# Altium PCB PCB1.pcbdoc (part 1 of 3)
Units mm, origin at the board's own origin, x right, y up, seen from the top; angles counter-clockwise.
Board outline 85.01 x 107.37 mm, 4 copper layers (Top Layer, Inner1, Inner2, Bottom Layer); 103 components, 145 nets, 660 pads, 277 vias.
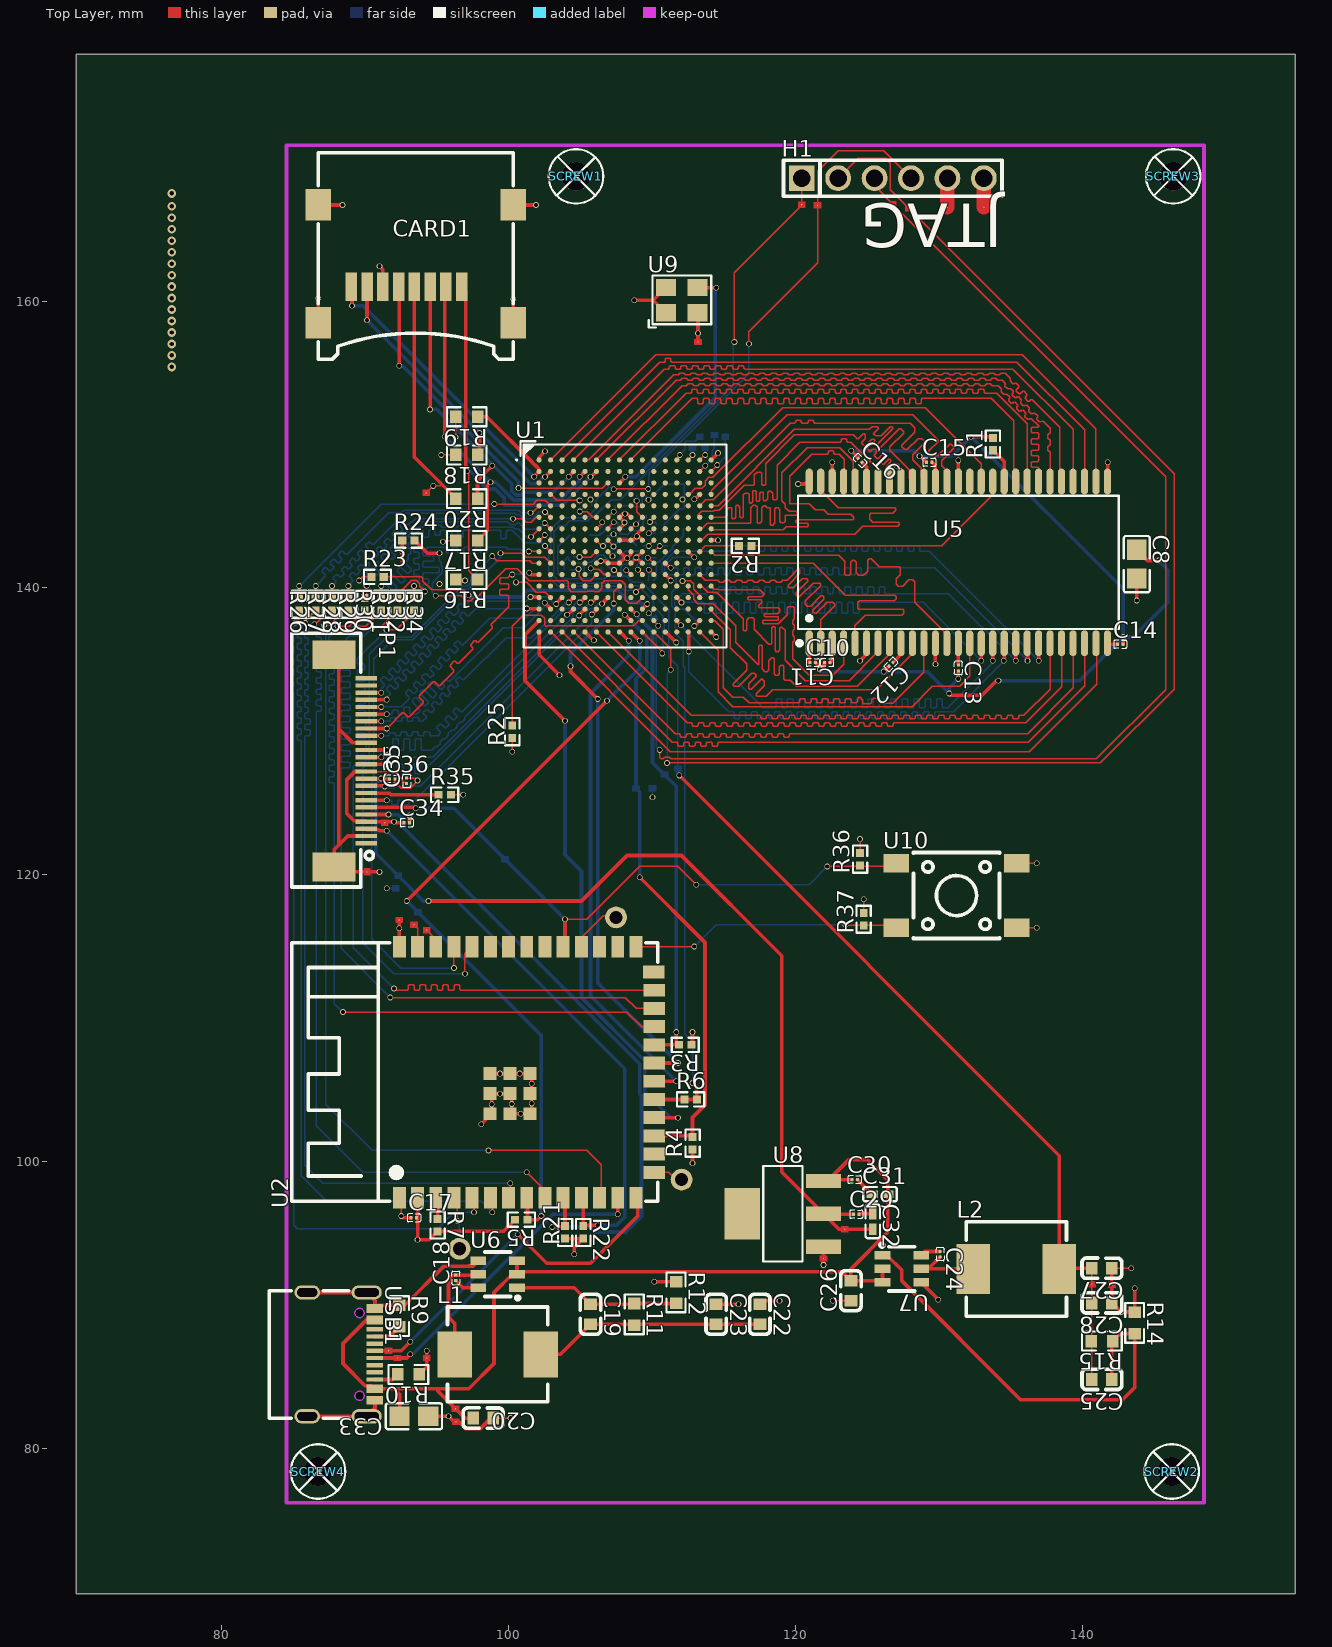
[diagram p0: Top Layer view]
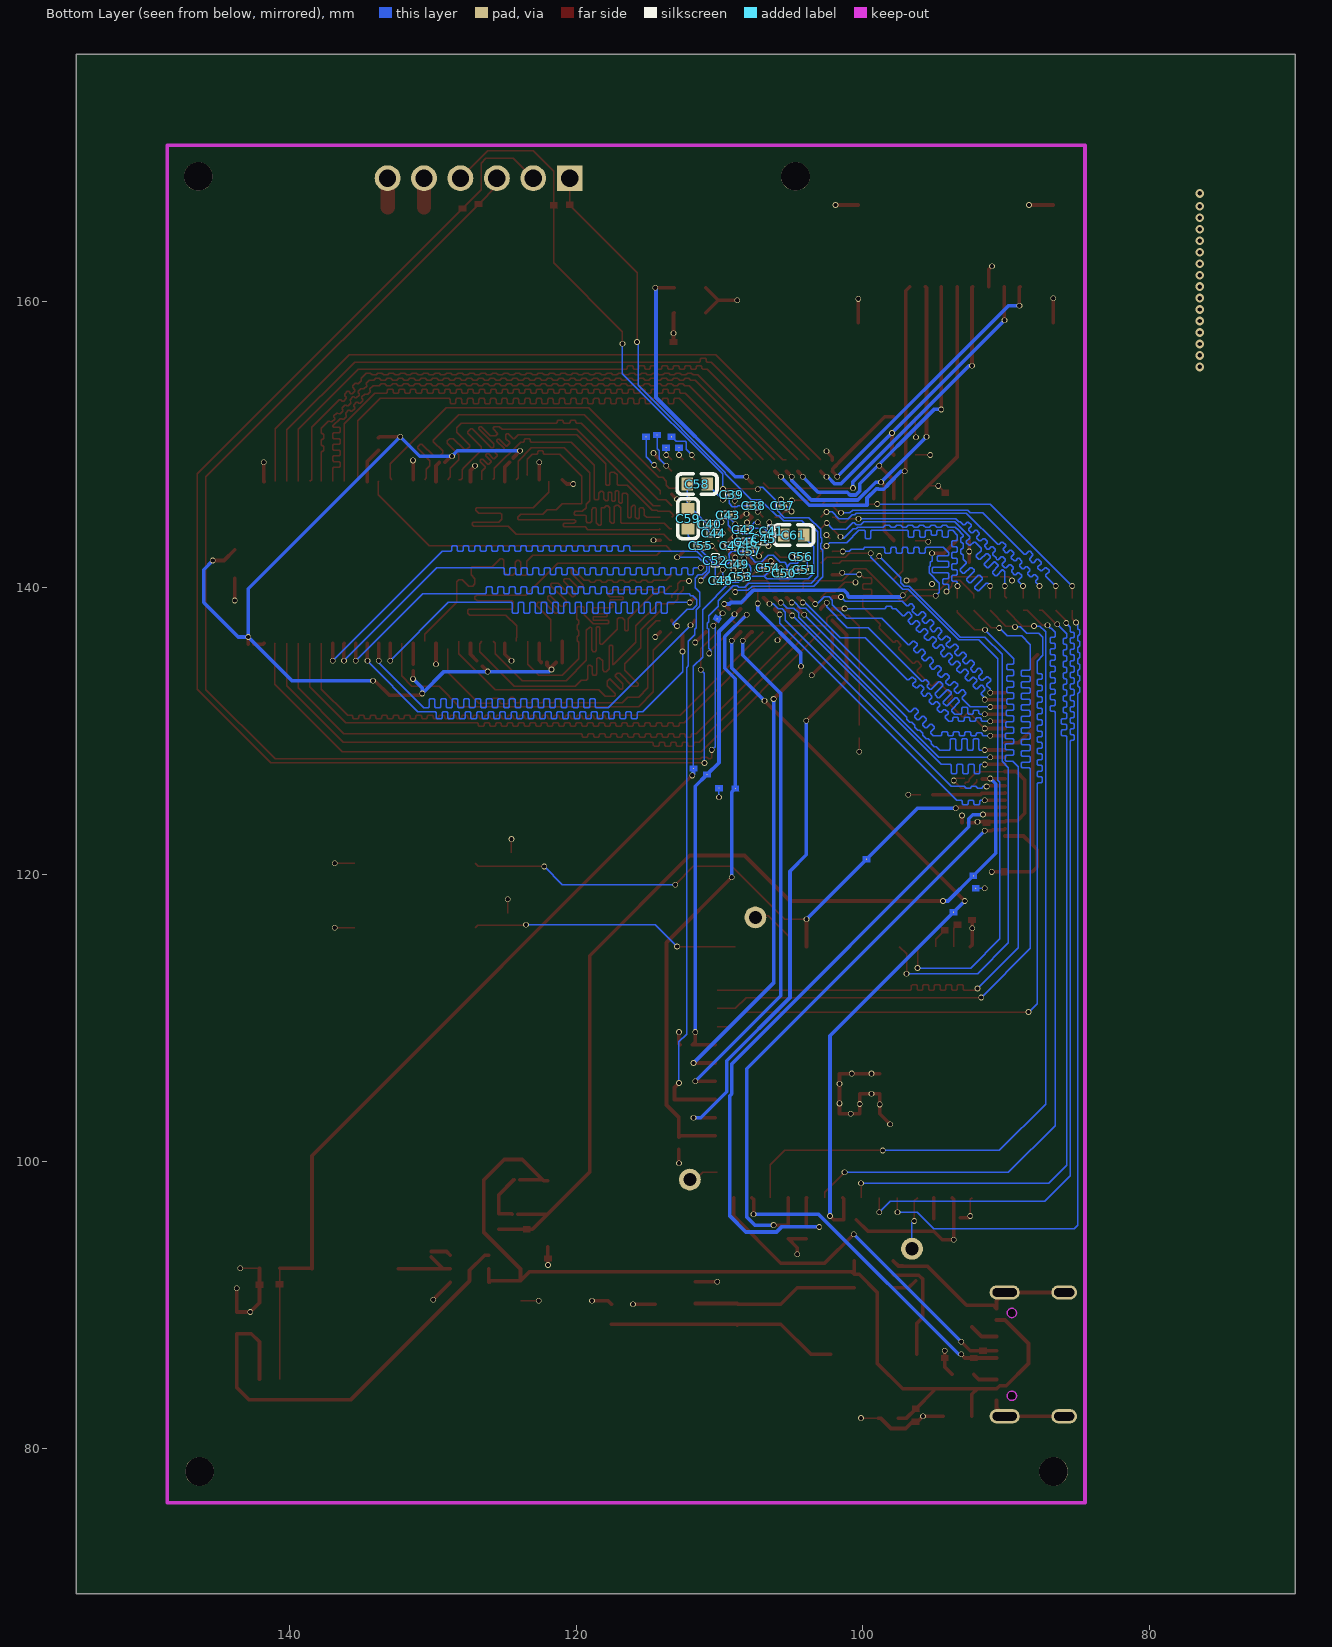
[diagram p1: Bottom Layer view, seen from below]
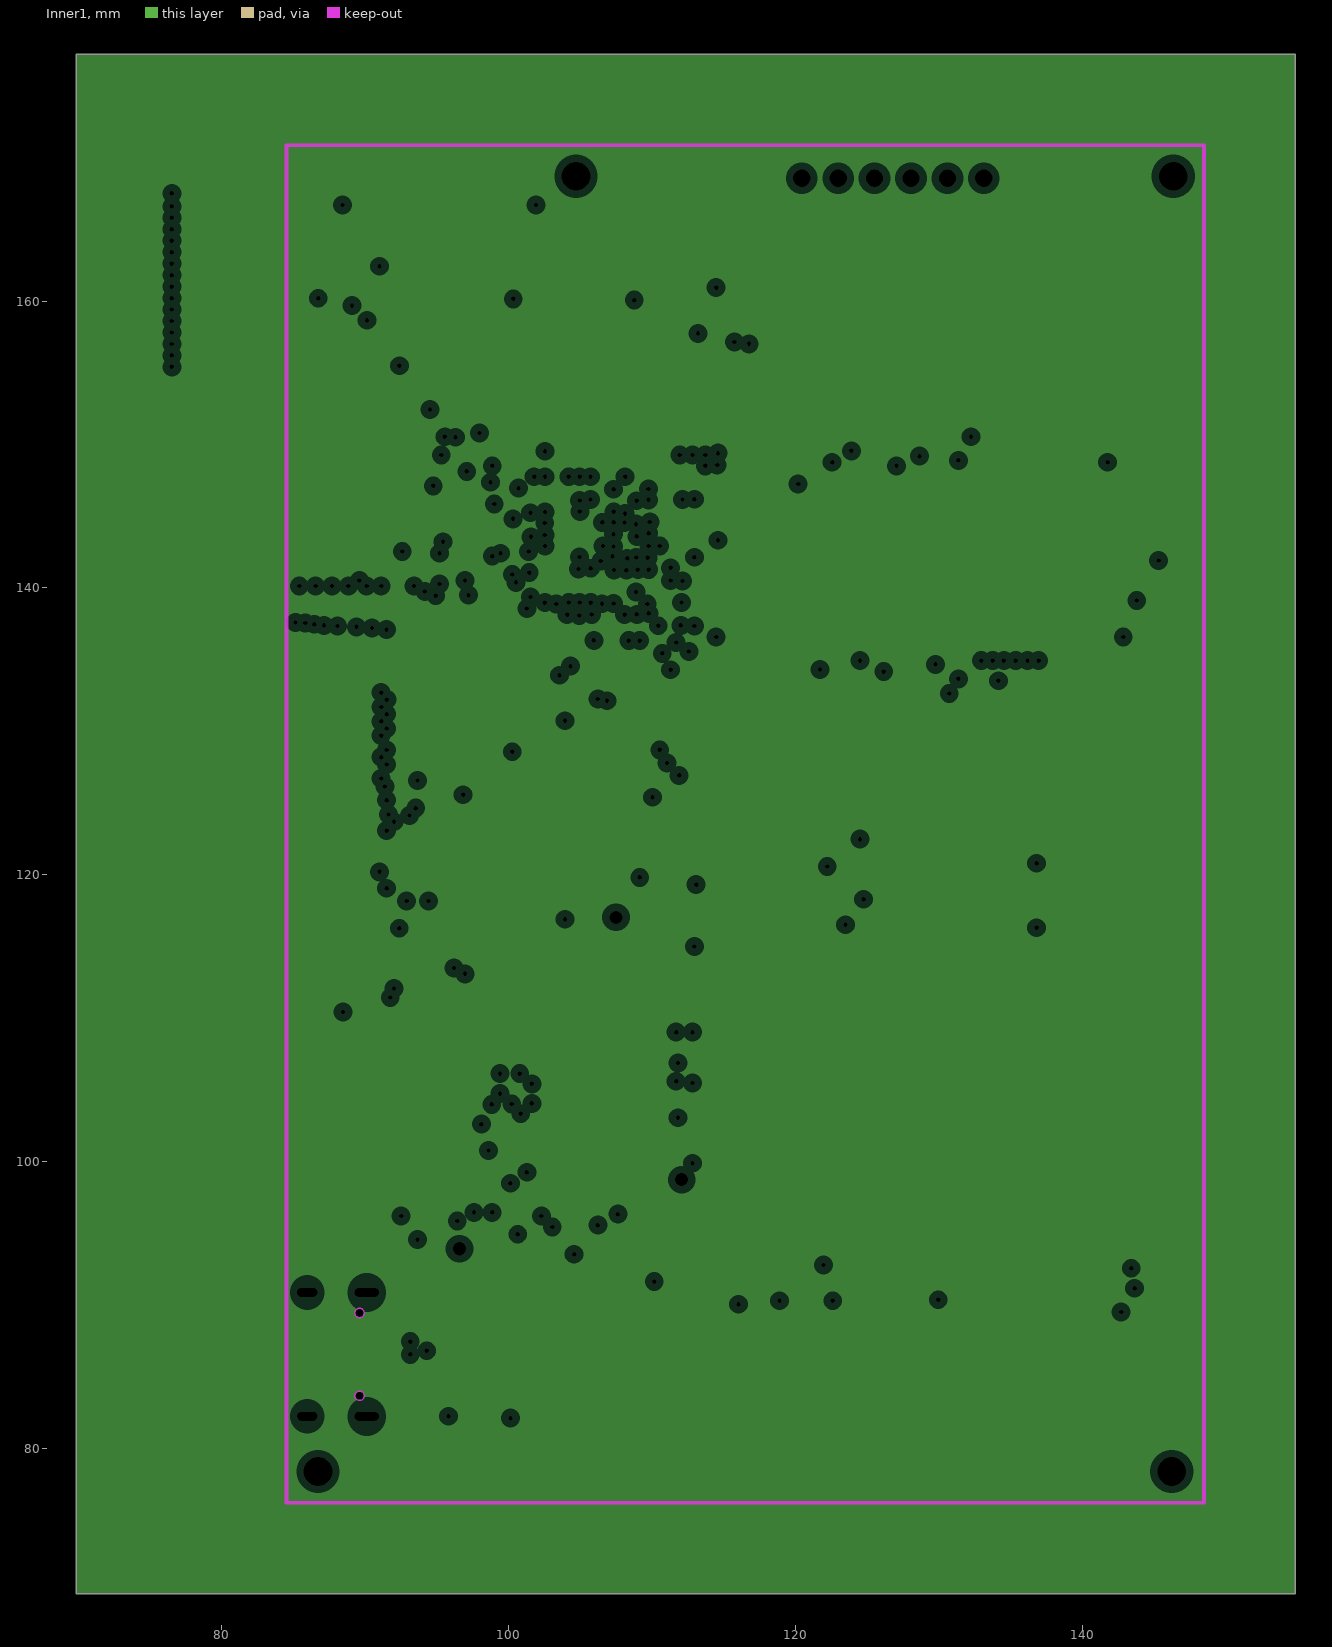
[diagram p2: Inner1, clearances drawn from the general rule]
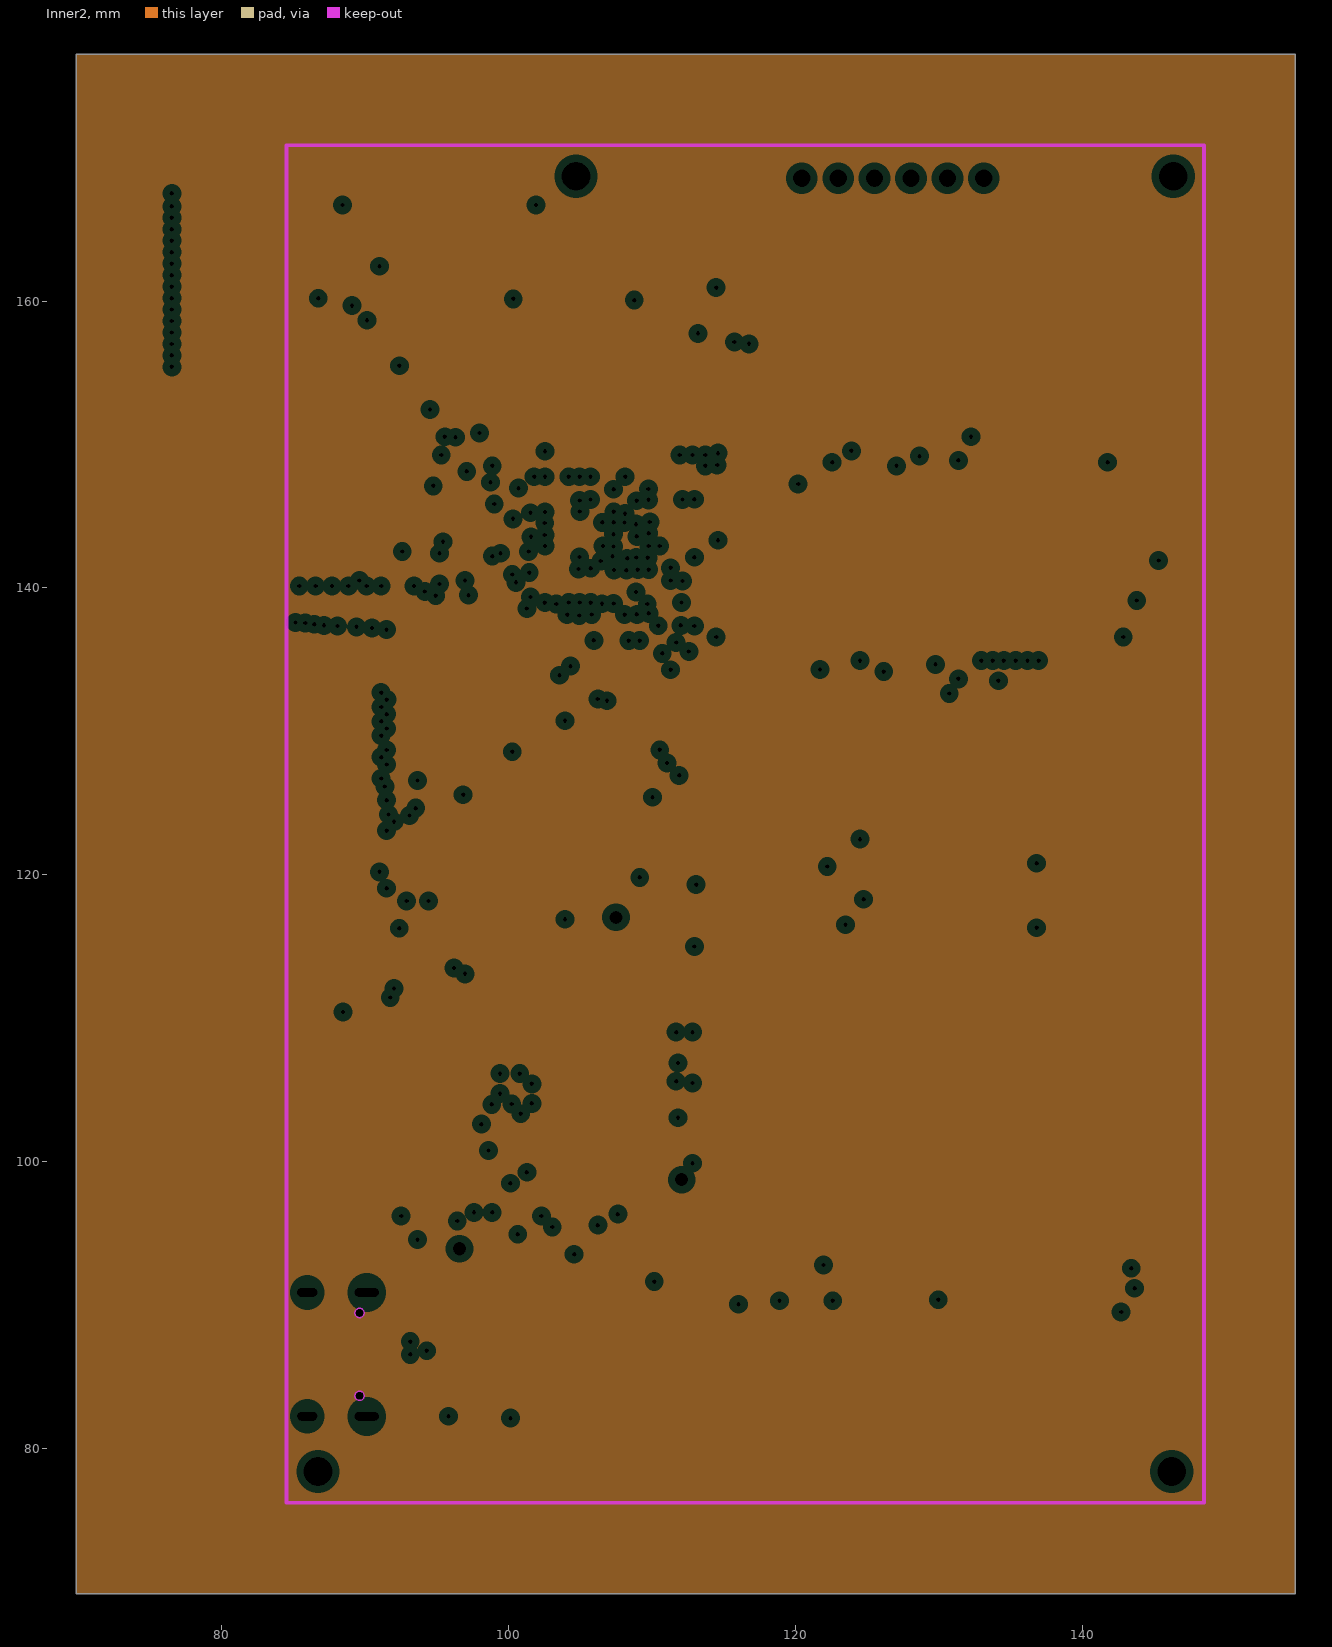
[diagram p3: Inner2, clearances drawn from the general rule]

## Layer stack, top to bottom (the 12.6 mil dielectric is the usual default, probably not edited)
Top Layer: signal copper (thickness not stored)
Dielectric: dielectric 0.32, FR-4, Dk 4.8
Inner1: plane copper (thickness not stored)
Dielectric: dielectric 0.32, FR-4, Dk 4.8
Inner2: plane copper (thickness not stored)
Dielectric: dielectric 0.32, FR-4, Dk 4.8
Bottom Layer: signal copper (thickness not stored)

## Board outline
154.856,69.85 69.85,69.85 69.85,177.216 154.856,177.216

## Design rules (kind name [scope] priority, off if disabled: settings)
BoardOutlineClearance copperThickness1oz [All] p0: genericclearance=0.254 ignorepadtopadclearanceinfootprint=FALSE except(0: Arc-SplitContinuation Track-SplitContinuation SMDPad-SplitContinuation THPad-SplitContinuation Via-SplitContinuation Fill-SplitContinuation Poly-SplitContinuation Region-SplitContinuation Text-SplitContinuation; 0.152: Track-CutoutEdge SMDPad-CutoutEdge THPad-CutoutEdge Via-CutoutEdge Region-CutoutEdge; 0.3: Track-OutlineEdge SMDPad-OutlineEdge THPad-OutlineEdge Via-OutlineEdge Fill-OutlineEdge Region-OutlineEdge Poly-OutlineEdge Text-OutlineEdge Fill-CutoutEdge)
BoardOutlineClearance copperThickness2oz [All] p0: genericclearance=0.254 ignorepadtopadclearanceinfootprint=FALSE except(0: Arc-SplitContinuation Track-SplitContinuation SMDPad-SplitContinuation THPad-SplitContinuation Via-SplitContinuation Fill-SplitContinuation Poly-SplitContinuation Region-SplitContinuation Text-SplitContinuation; 0.152: Track-CutoutEdge SMDPad-CutoutEdge THPad-CutoutEdge Via-CutoutEdge Region-CutoutEdge; 0.3: Track-OutlineEdge SMDPad-OutlineEdge THPad-OutlineEdge Via-OutlineEdge Fill-OutlineEdge Region-OutlineEdge Poly-OutlineEdge Text-OutlineEdge Fill-CutoutEdge)
Clearance copperThickness1oz [(InNet('SD_A0') OR InNet('SD_A1') OR InNet('SD_A2') OR InNet('SD_A3') OR InNet('SD_A4') OR InNet('SD_A5') OR InNet('SD_A6') OR InNet('SD_A7') OR InNet('SD_A8') OR InNet('SD_A9') OR InNet('SD_A10') OR InNet('SD_A11') OR InNet('SD_A12') OR InNet('SD_DQ15') OR InNet('SD_DQ14') OR InNet('SD_DQ8') OR InNet('SD_BA0') OR InNet('SD_BA1') OR InNet('SD_DQ9') OR InNet('SD_DQ7') OR InNet('SD_CLK') OR InNet('SD_WE_N') OR InNet('SD_DQ10') OR InNet('SD_CAS_N') OR InNet('SD_DQM1') OR InNet('SD_DQ2') OR InNet('SD_DQ3') OR InNet('SD_DQ11') OR InNet('SD_DQ12') OR InNet('SD_DQ13') OR InNet('SD_DQ0') OR InNet('SD_DQ1') OR InNet('SD_CS_N') OR InNet('SD_RAS_N') OR InNet('SD_DQ4') OR InNet('SD_DQ6') OR InNet('$1N9241') OR InNet('$1N9192') OR InNet('GND') OR InNet('$1N9142') OR InNet('SD_DQ5') OR InNet('$1N9091') OR InNet('SD_DQM0') OR InNet('$1N9039') OR InNet('$1N8986') OR InNet('$1N8318') OR InNet('$1N9437') OR InNet('$1N9341') OR InNet('+3V3') OR InNet('$1N11348') OR InNet('DOUT') OR InNet('DIN') OR InNet('CCLK') OR InNet('DONE') OR InNet('PROGRAMN') OR InNet('INITN') OR InNet('$1N11975') OR InNet('DN') OR InNet('DP') OR InNet('$1N14459') OR InNet('$1N14416') OR InNet('$1N14567') OR InNet('+5V') OR InNet('$1N16833') OR InNet('$1N16832') OR InNet('+1V1') OR InNet('$1N16834') OR InNet('+1V8') OR InNet('$1N17349') OR InNet('$1N12557') OR InNet('$1N12553') OR InNet('M_D2') OR InNet('M_D3') OR InNet('M_CMD') OR InNet('M_CLK') OR InNet('M_D0') OR InNet('M_D1') OR InNet('SDA') OR InNet('SCL') OR InNet('RESET') OR InNet('VSYNC') OR InNet('HREF') OR InNet('Y9') OR InNet('MCLK') OR InNet('Y8') OR InNet('Y7') OR InNet('PCLK') OR InNet('Y6') OR InNet('Y2') OR InNet('Y5') OR InNet('Y3') OR InNet('Y4') OR InNet('$1N14571') OR InNet('$1N24422') OR InNet('$1N24377') OR InNet('$1N24492') OR InNet('CRYSTAL') OR InNet('SSPI_CS_N') OR InNet('D0') OR InNet('D1') OR InNet('D2') OR InNet('D4') OR InNet('D3') OR InNet('D5') OR InNet('D6') OR InNet('D7') OR InNet('RX') OR InNet('TX') OR InNet('$1N29790') OR InNet('$1N29833') OR InNet('$1N29916') OR InNet('$1N29959') OR InNet('$1N30002') OR InNet('$1N30085') OR InNet('$1N30089') OR InNet('$1N30093') OR InNet('TDO') OR InNet('TDI') OR InNet('TMS') OR InNet('TCK') OR InNet('$1N33205') OR InNet('PROGRAM') OR InNet('$1N36431') OR InNet('$1N36646') OR InNet('$1N36895') OR InNet('$1N37600') OR InNet('$1N37295') OR InNet('$1N36495') OR InNet('$1N36690') OR InNet('$1N36953') OR InNet('$1N37637') OR InNet('$1N37245') OR InNet('$1N37470') OR InNet('$1N36752') OR InNet('$1N37409') OR InNet('$1N36552') OR InNet('$1N37361') OR InNet('$1N36571') OR InNet('$1N36807') OR InNet('$1N37097') OR InNet('$1N37518') OR InNet('$1N37345') OR InNet('$1N37150') OR InNet('$1N47813') OR InNet('$1N41066'))] p1: gap=0.178 ignorepadtopadclearanceinfootprint=FALSE except(0.099: Track-Track; 0.152: Track-SMDPad SMDPad-SMDPad Track-THPad SMDPad-THPad THPad-THPad Track-Via SMDPad-Via THPad-Via Via-Via SMDPad-Fill THPad-Fill Via-Fill Fill-Fill Track-Region SMDPad-Region THPad-Region Via-Region Region-Region Track-Poly SMDPad-Poly THPad-Poly Via-Poly Fill-Poly Region-Poly Poly-Poly Track-Text SMDPad-Text THPad-Text Via-Text Fill-Text Region-Text Poly-Text Text-Text; 0.175: Track-Hole SMDPad-Hole THPad-Hole Via-Hole Fill-Hole Region-Hole Poly-Hole Text-Hole Sheet-Hole; 0.3: Track-Fill Fill-Region Track-Sheet SMDPad-Sheet THPad-Sheet Via-Sheet Fill-Sheet Region-Sheet Poly-Sheet Text-Sheet)
Clearance copperThickness2oz [All] p1: gap=0.178 ignorepadtopadclearanceinfootprint=FALSE except(0.152: Track-SMDPad SMDPad-SMDPad Track-THPad SMDPad-THPad THPad-THPad Track-Via SMDPad-Via THPad-Via Via-Via SMDPad-Fill THPad-Fill Via-Fill Fill-Fill Track-Region SMDPad-Region THPad-Region Via-Region Region-Region Track-Poly SMDPad-Poly THPad-Poly Via-Poly Fill-Poly Region-Poly Poly-Poly Track-Text SMDPad-Text THPad-Text Via-Text Fill-Text Region-Text Poly-Text Text-Text; 0.175: Track-Hole SMDPad-Hole THPad-Hole Via-Hole Fill-Hole Region-Hole Poly-Hole Text-Hole Sheet-Hole; 0.203: Track-Track; 0.3: Track-Fill Fill-Region Track-Sheet SMDPad-Sheet THPad-Sheet Via-Sheet Fill-Sheet Region-Sheet Poly-Sheet Text-Sheet)
DiffPairsRouting differentialPair [All] p1: maxuncoupledlength=10 minlimit=6 maxlimit=6 mostfreqgap=6 toplayer_minwidth=5 toplayer_prefwidth=10 toplayer_maxwidth=100 bottomlayer_minwidth=5 bottomlayer_prefwidth=10 bottomlayer_maxwidth=100
PasteMaskExpansion pasteMaskExpansion [All] p1: expansion=0
PlaneConnect innerPlane [All] p1: planeconnectstyle=Relief reliefexpansion=0.508 reliefentries=4 reliefconductorwidth=0.254 reliefairgap=0.254
PolygonConnect copperRegion [All] p1: connectstyle=Relief reliefentries=4 reliefconductorwidth=10 polygonreliefangle="90 Angle" airgapwidth=10
RoutingVias viaSize [All] p1: viastyle="Through Hole" holewidth=11.811 minholewidth=11.811 maxholewidth=248.0314 width=15.748 minwidth=15.748 maxwidth=393.7008
SolderMaskExpansion solderMaskExpansion [All] p1: useseparateexpansions=TRUE expansion=2 expansionbottom=2
Width copperThickness1oz [All] p1: maxlimit=100 minlimit=4 preferedwidth=4
Width copperThickness2oz [All] p1: maxlimit=100 minlimit=8 preferedwidth=10

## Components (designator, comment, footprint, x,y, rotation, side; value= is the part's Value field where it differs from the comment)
C8 "CL21A476MQYNNNE" C0805 143.815,141.656 r270 top
C10 "GRM022R60J104KE15D" C01005 121.209,134.798 r0 top
C11 "GRM022R60J104KE15D" C01005 122.225,134.798 r180 top
C12 "GRM022R60J104KE15D" C01005 126.67,134.671 r225 top
C13 "GRM022R60J104KE15D" C01005 131.369,134.417 r270 top
C14 "GRM022R60J104KE15D" C01005 142.672,136.068 r0 top
C15 "GRM022R60J104KE15D" C01005 129.337,148.768 r0 top
C16 "GRM022R60J104KE15D" C01005 124.511,148.895 r315 top
C17 "GRM022R60J104KE15D" C01005 93.396,96.063 r0 top
C18 "GRM022R60J104KE15D" C01005 96.317,91.872 r90 top
C19 "TCC0603X7R104K500CT" C0603 105.715,89.332 r270 top
C20 "TCC0603X5R226M6R3CT" C0603 98.222,82.093 r180 top
C22 "TCC0603X5R226M6R3CT" C0603 117.526,89.332 r270 top
C23 "TCC0603X5R226M6R3CT" C0603 114.478,89.332 r270 top
C24 "GRM022R60J104KE15D" C01005 130.099,93.523 r270 top
C25 "TCC0603X7R104K500CT" C0603 141.381,84.799 r180 top
C26 "TCC0603X5R226M6R3CT" C0603 123.876,90.983 r90 top
C27 "TCC0603X5R226M6R3CT" C0603 141.381,92.546 r180 top
C28 "TCC0603X5R226M6R3CT" C0603 141.381,90.133 r180 top
C29 "GRM022R60J104KE15D" C01005 124.257,96.317 r0 top
C30 "GRM022R60J104KE15D" C01005 124.13,98.73 r0 top
C31 "GRM155R60J106ME44D" C0402 125.908,97.714 r0 top
C32 "GRM155R60J106ME44D" C0402 125.4,95.809 r270 top
C33 "CL21A476MQYNNNE" C0805 93.396,82.22 r180 top
C34 "GRM022R60J104KE15D" C01005 92.888,123.622 r0 top
C35 "GRM022R60J104KE15D" C01005 92.888,126.543 r90 top
C36 "GRM022R60J104KE15D" C01005 91.872,126.67 r0 top
C37 "GRM022R60J104KE15D" C01005 105.588,145.72 r180 bottom
C38 "GRM022R60J104KE15D" C01005 107.62,145.72 r180 bottom
C39 "GRM022R60J104KE15D" C01005 109.144,146.482 r180 bottom
C40 "GRM022R60J104KE15D" C01005 110.668,144.45 r180 bottom
C41 "GRM022R60J104KE15D" C01005 106.35,143.942 r90 bottom
C42 "GRM022R60J104KE15D" C01005 108.255,144.069 r180 bottom
C43 "GRM022R60J104KE15D" C01005 109.398,145.085 r180 bottom
C44 "GRM022R60J104KE15D" C01005 110.414,143.815 r180 bottom
C45 "GRM022R60J104KE15D" C01005 106.858,143.434 r270 bottom
C46 "GRM022R60J104KE15D" C01005 108.128,143.18 r180 bottom
C47 "GRM022R60J104KE15D" C01005 109.144,142.926 r0 bottom
C48 "GRM022R60J104KE15D" C01005 109.906,140.513 r0 bottom
C49 "GRM022R60J104KE15D" C01005 108.763,141.656 r180 bottom
C50 "GRM022R60J104KE15D" C01005 105.486,141.021 r180 bottom
C51 "GRM022R60J104KE15D" C01005 104.064,141.275 r180 bottom
C52 "GRM022R60J104KE15D" C01005 110.287,141.91 r270 bottom
C53 "GRM022R60J104KE15D" C01005 108.509,140.767 r180 bottom
C54 "GRM022R60J104KE15D" C01005 106.604,141.402 r180 bottom
C55 "GRM022R60J104KE15D" C01005 111.303,142.926 r0 bottom
C56 "GRM022R60J104KE15D" C01005 104.318,142.164 r180 bottom
C57 "GRM022R60J104KE15D" C01005 107.874,142.545 r0 bottom
C58 "TCC0603X5R226M6R3CT" C0603 111.557,147.244 r180 bottom
C59 "TCC0603X5R226M6R3CT" C0603 112.192,144.831 r90 bottom
C61 "TCC0603X5R226M6R3CT" C0603 104.826,143.688 r180 bottom
CARD1 "DS1139-06-08SS4BSR" TF-SMD_DS1139-06-08SS4BSR 93.523,162.611 r0 top
H1 "2.54-1x6P直针" HDR-TH_6P-P2.54-V-M-1 126.797,168.58 r0 top
L1 "FXL0630-6R8-M" IND-SMD_L7.0-W6.6 99.238,86.538 r0 top
L2 "FXL0630-100-M" IND-SMD_L7.3-W6.8 135.417,92.501 r0 top
P1 "AFC07-S24FCC-00" FPC-SMD_AFC07-S24FCC-00 88.951,127.94 r270 top
R1 "0402WGF1002TCE" R0402 133.782,150.038 r90 top
R2 "0402WGF330JTCE" R0402 116.51,142.926 r180 top
R3 "0402WGF1002TCE" R0402 112.319,108.128 r180 top
R4 "0402WGF1002TCE" R0402 112.827,101.27 r90 top
R5 "0402WGF1002TCE" R0402 100.889,95.936 r180 top
R6 "0402WGF330JTCE" R0402 112.7,104.318 r0 top
R7 "0402WGF1002TCE" R0402 95.047,95.555 r270 top
R9 "0603WAF5101T5E" R0603 92.38,89.205 r270 top
R10 "0603WAF5101T5E" R0603 93.015,85.141 r180 top
R11 "FRC0603F1963TS" R0603 108.763,89.332 r270 top
R12 "FRC0603F6202TS" R0603 111.684,90.856 r270 top
R14 "FRC0603F6202TS" R0603 143.667,88.736 r270 top
R15 "0603WAF2322T5E" R0603 141.381,87.466 r180 top
R16 "FRC0603F6202TS" R0603 97.075,140.589 r180 top
R17 "FRC0603F6202TS" R0603 97.079,143.307 r180 top
R18 "FRC0603F6202TS" R0603 97.079,149.276 r180 top
R19 "FRC0603F6202TS" R0603 97.079,151.943 r180 top
R20 "FRC0603F6202TS" R0603 97.079,146.228 r180 top
R21 "0402WGF1002TCE" R0402 103.937,95.047 r270 top
R22 "0402WGF1002TCE" R0402 105.207,95.047 r270 top
R23 "0402WGF1002TCE" R0402 90.856,140.767 r0 top
R24 "0402WGF1002TCE" R0402 93.015,143.307 r0 top
R25 "0402WGF1002TCE" R0402 100.254,129.972 r90 top
R26 "0402WGF330JTCE" R0402 85.395,138.862 r270 top
R27 "0402WGF330JTCE" R0402 86.538,138.862 r270 top
R28 "0402WGF330JTCE" R0402 87.681,138.862 r270 top
R29 "0402WGF330JTCE" R0402 88.824,138.862 r270 top
R30 "0402WGF330JTCE" R0402 89.967,138.862 r270 top
R31 "0402WGF330JTCE" R0402 91.11,138.862 r270 top
R32 "0402WGF330JTCE" R0402 92.253,138.862 r270 top
R34 "0402WGF330JTCE" R0402 93.396,138.862 r270 top
R35 "0402WGF1002TCE" R0402 95.541,125.576 r0 top
R36 "0402WGF1002TCE" R0402 124.511,121.082 r90 top
R37 "0402WGF1002TCE" R0402 124.765,116.891 r90 top
SCREW1 "Screw-Hole-M2" Screw-Hole-M2 104.699,168.707 r0 top
SCREW2 "Screw-Hole-M2" Screw-Hole-M2 146.255,78.368 r0 top
SCREW3 "Screw-Hole-M2" Screw-Hole-M2 146.355,168.707 r0 top
SCREW4 "Screw-Hole-M2" Screw-Hole-M2 86.707,78.368 r0 top
U1 "LFE5U-25F-6BG256C" CABGA-256_L14.0-W14.0-R16-C16-P0.80-TL 108.128,142.926 r0 top
U2 "ESP32-S3-WROOM-1-N16R2" WIRELM-SMD_ESP32-S3-WROOM-1 101.27,106.223 r90 top
U5 "W9825G6KH-6" TSOP-54_L22.2-W10.2-P0.80-LS11.8-BL 131.369,141.783 r0 top
U6 "AP63200WU-7" SOT-23-6_L2.9-W1.6-P0.95-LS2.8-BR 99.238,92.126 r0 top
U7 "AP63200WU-7" SOT-23-6_L2.9-W1.6-P0.95-LS2.8-BR 127.432,92.507 r180 top
U8 "AMS1117-1.8_C6185" SOT-223-4_L6.5-W3.5-P2.30-LS7.0-BR 119.13,96.346 r0 top
U9 "XOS32024000LT00351005" OSC-SMD_4P-L3.2-W2.5-BL 112.065,160.071 r0 top
U10 "TPS645-5NC60" SW-SMD_4P-L6.0-W6.0-P4.50-LS9.2 131.242,118.542 r0 top
USB1 "TYPE-C16PIN" USB-C-SMD_TYPE-C16PIN 88.316,86.538 r270 top

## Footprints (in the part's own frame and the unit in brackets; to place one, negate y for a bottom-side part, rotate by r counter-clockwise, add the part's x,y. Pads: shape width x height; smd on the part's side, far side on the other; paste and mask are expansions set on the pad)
C0402 [mm]
  rect 0.79x0.54 smd: 1(-0.545,0) 2(0.545,0)
  silkscreen extent -1.17,-0.5 1.17,0.5
C0603 [mm]
  rect 0.8x0.9 smd: 1(-0.7,0) 2(0.7,0)
  silkscreen extent -1.39,-0.71 1.39,0.71
C0805 [mm]
  rect 1.41x1.35 smd: 1(-1,0) 2(1,0)
  silkscreen extent -1.96,-0.9 1.96,0.9
C01005 [mm]
  rect 0.21x0.22 smd: 1(-0.195,0) 2(0.195,0)
  silkscreen extent -0.46,-0.27 0.46,0.27
CABGA-256_L14.0-W14.0-R16-C16-P0.80-TL [mm]
  round 0.36 smd: A1(-6,6) A2(-5.2,6) A3(-4.4,6) A4(-3.6,6) A5(-2.8,6) A6(-2,6) A7(-1.2,6) A8(-0.4,6) A9(0.4,6) A10(1.2,6) A11(2,6) A12(2.8,6) A13(3.6,6) A14(4.4,6) A15(5.2,6) A16(6,6) B1(-6,5.2) B2(-5.2,5.2) B3(-4.4,5.2) B4(-3.6,5.2) B5(-2.8,5.2) B6(-2,5.2) B7(-1.2,5.2) B8(-0.4,5.2) B9(0.4,5.2) B10(1.2,5.2) B11(2,5.2) B12(2.8,5.2) B13(3.6,5.2) B14(4.4,5.2) B15(5.2,5.2) B16(6,5.2) C1(-6,4.4) C2(-5.2,4.4) C3(-4.4,4.4) C4(-3.6,4.4) C5(-2.8,4.4) C6(-2,4.4) C7(-1.2,4.4) C8(-0.4,4.4) C9(0.4,4.4) C10(1.2,4.4) C11(2,4.4) C12(2.8,4.4) C13(3.6,4.4) C14(4.4,4.4) C15(5.2,4.4) C16(6,4.4) D1(-6,3.6) D2(-5.2,3.6) D3(-4.4,3.6) D4(-3.6,3.6) D5(-2.8,3.6) D6(-2,3.6) D7(-1.2,3.6) D8(-0.4,3.6) D9(0.4,3.6) D10(1.2,3.6) D11(2,3.6) D12(2.8,3.6) D13(3.6,3.6) D14(4.4,3.6) D15(5.2,3.6) D16(6,3.6) E1(-6,2.8) E2(-5.2,2.8) E3(-4.4,2.8) E4(-3.6,2.8) E5(-2.8,2.8) E6(-2,2.8) E7(-1.2,2.8) E8(-0.4,2.8) E9(0.4,2.8) E10(1.2,2.8) E11(2,2.8) E12(2.8,2.8) E13(3.6,2.8) E14(4.4,2.8) E15(5.2,2.8) E16(6,2.8) F1(-6,2) F2(-5.2,2) F3(-4.4,2) F4(-3.6,2) F5(-2.8,2) F6(-2,2) F7(-1.2,2) F8(-0.4,2) F9(0.4,2) F10(1.2,2) F11(2,2) F12(2.8,2) F13(3.6,2) F14(4.4,2) F15(5.2,2) F16(6,2) G1(-6,1.2) G2(-5.2,1.2) G3(-4.4,1.2) G4(-3.6,1.2) G5(-2.8,1.2) G6(-2,1.2) G7(-1.2,1.2) G8(-0.4,1.2) G9(0.4,1.2) G10(1.2,1.2) G11(2,1.2) G12(2.8,1.2) G13(3.6,1.2) G14(4.4,1.2) G15(5.2,1.2) G16(6,1.2) H1(-6,0.4) H2(-5.2,0.4) H3(-4.4,0.4) H4(-3.6,0.4) H5(-2.8,0.4) H6(-2,0.4) H7(-1.2,0.4) H8(-0.4,0.4) H9(0.4,0.4) H10(1.2,0.4) H11(2,0.4) H12(2.8,0.4) H13(3.6,0.4) H14(4.4,0.4) H15(5.2,0.4) H16(6,0.4) J1(-6,-0.4) J2(-5.2,-0.4) J3(-4.4,-0.4) J4(-3.6,-0.4) J5(-2.8,-0.4) J6(-2,-0.4) J7(-1.2,-0.4) J8(-0.4,-0.4) J9(0.4,-0.4) J10(1.2,-0.4) J11(2,-0.4) J12(2.8,-0.4) J13(3.6,-0.4) J14(4.4,-0.4) J15(5.2,-0.4) J16(6,-0.4) K1(-6,-1.2) K2(-5.2,-1.2) K3(-4.4,-1.2) K4(-3.6,-1.2) K5(-2.8,-1.2) K6(-2,-1.2) K7(-1.2,-1.2) K8(-0.4,-1.2) K9(0.4,-1.2) K10(1.2,-1.2) K11(2,-1.2) K12(2.8,-1.2) K13(3.6,-1.2) K14(4.4,-1.2) K15(5.2,-1.2) K16(6,-1.2) L1(-6,-2) L2(-5.2,-2) L3(-4.4,-2) L4(-3.6,-2) L5(-2.8,-2) L6(-2,-2) L7(-1.2,-2) L8(-0.4,-2) L9(0.4,-2) L10(1.2,-2) L11(2,-2) L12(2.8,-2) L13(3.6,-2) L14(4.4,-2) L15(5.2,-2) L16(6,-2) M1(-6,-2.8) M2(-5.2,-2.8) M3(-4.4,-2.8) M4(-3.6,-2.8) M5(-2.8,-2.8) M6(-2,-2.8) M7(-1.2,-2.8) M8(-0.4,-2.8) M9(0.4,-2.8) M10(1.2,-2.8) M11(2,-2.8) M12(2.8,-2.8) M13(3.6,-2.8) M14(4.4,-2.8) M15(5.2,-2.8) M16(6,-2.8) N1(-6,-3.6) N2(-5.2,-3.6) N3(-4.4,-3.6) N4(-3.6,-3.6) N5(-2.8,-3.6) N6(-2,-3.6) N7(-1.2,-3.6) N8(-0.4,-3.6) N9(0.4,-3.6) N10(1.2,-3.6) N11(2,-3.6) N12(2.8,-3.6) N13(3.6,-3.6) N14(4.4,-3.6) N15(5.2,-3.6) N16(6,-3.6) P1(-6,-4.4) P2(-5.2,-4.4) P3(-4.4,-4.4) P4(-3.6,-4.4) P5(-2.8,-4.4) P6(-2,-4.4) P7(-1.2,-4.4) P8(-0.4,-4.4) P9(0.4,-4.4) P10(1.2,-4.4) P11(2,-4.4) P12(2.8,-4.4) P13(3.6,-4.4) P14(4.4,-4.4) P15(5.2,-4.4) P16(6,-4.4) R1(-6,-5.2) R2(-5.2,-5.2) R3(-4.4,-5.2) R4(-3.6,-5.2) R5(-2.8,-5.2) R6(-2,-5.2) R7(-1.2,-5.2) R8(-0.4,-5.2) R9(0.4,-5.2) R10(1.2,-5.2) R11(2,-5.2) R12(2.8,-5.2) R13(3.6,-5.2) R14(4.4,-5.2) R15(5.2,-5.2) R16(6,-5.2) T1(-6,-6) T2(-5.2,-6) T3(-4.4,-6) T4(-3.6,-6) T5(-2.8,-6) T6(-2,-6) T7(-1.2,-6) T8(-0.4,-6) T9(0.4,-6) T10(1.2,-6) T11(2,-6) T12(2.8,-6) T13(3.6,-6) T14(4.4,-6) T15(5.2,-6) T16(6,-6)
  silkscreen extent -7.63,-7.08 7.08,7.3
FPC-SMD_AFC07-S24FCC-00 [mm]
  rect 0.3x1.5 smd: 1(5.745,1.129) 2(5.245,1.129) 3(4.746,1.129) 4(4.245,1.129) 5(3.746,1.129) 6(3.245,1.129) 7(2.746,1.129) 8(2.245,1.129) 9(1.746,1.129) 10(1.245,1.129) 11(0.746,1.129) 12(0.245,1.129) 13(-0.254,1.129) 14(-0.755,1.129) 15(-1.251,1.13) 16(-1.754,1.13) 17(-2.254,1.128) 18(-2.754,1.129) 19(-3.254,1.129) 20(-3.756,1.132) 21(-4.256,1.132) 22(-4.756,1.132) 23(-5.256,1.132) 24(-5.756,1.132)
  rect 2x3 smd: 25(-7.401,-1.132) 26(7.401,-1.125)
  silkscreen extent -8.89,-4.07 8.8,1.61
HDR-TH_6P-P2.54-V-M-1 [mm]
  rect 1.8x1.8 hole 1.2: 1(-6.35,0)
  round 1.8 hole 1.2: 2(-3.81,0) 3(-1.27,0) 4(1.27,0) 5(3.81,0) 6(6.35,0)
  silkscreen extent -7.62,-1.25 7.62,1.25
IND-SMD_L7.0-W6.6 [mm]
  rect 2.4x3.2 smd: 1(-3,0) 2(3,0)
  silkscreen extent -3.5,-3.3 3.5,3.3
IND-SMD_L7.3-W6.8 [mm]
  rect 2.35x3.5 smd: 1(-3,0) 2(3,0)
  silkscreen extent -3.5,-3.3 3.5,3.3
OSC-SMD_4P-L3.2-W2.5-BL [mm]
  rect 1.4x1.2 smd: 1(-1.1,-0.875) 2(1.1,-0.875) 3(1.1,0.875) 4(-1.1,0.875)
  silkscreen extent -2.29,-1.9 2.07,1.72
R0402 [mm]
  rect 0.566x0.54 smd: 1(-0.433,0) 2(0.433,0)
  silkscreen extent -0.94,-0.5 0.94,0.5
R0603 [mm]
  rect 0.806x0.864 smd: 1(-0.753,0) 2(0.753,0)
  silkscreen extent -1.39,-0.66 1.39,0.66
Screw-Hole-M2 [mm]
  round 2 hole 2: 1(0,0)
  silkscreen extent -1.9,-1.9 1.9,1.9
SOT-23-6_L2.9-W1.6-P0.95-LS2.8-BR [mm]
  rect 1.1x0.6 smd: 1(1.35,-0.95) 2(1.35,0) 3(1.35,0.95) 4(-1.35,0.95) 5(-1.35,0) 6(-1.35,-0.95)
  silkscreen extent -0.9,-1.78 1.52,1.55
SOT-223-4_L6.5-W3.5-P2.30-LS7.0-BR [mm]
  rect 2.47x0.98 smd: 1(2.835,-2.3) 2(2.835,0) 3(2.835,2.3)
  rect 2.47x3.6 smd: 4(-2.835,0)
  silkscreen extent -1.37,-3.33 1.37,3.33
SW-SMD_4P-L6.0-W6.0-P4.50-LS9.2 [mm]
  rect 1.8x1.3 smd: 1(-4.2,2.25) 2(4.2,2.25) 3(-4.2,-2.25) 4(4.2,-2.25)
  silkscreen extent -3,-3 3,3
TF-SMD_DS1139-06-08SS4BSR [mm]
  rect 0.8x2 smd: 1(3.2,-1.6) 2(2.1,-1.6) 3(1,-1.6) 4(-0.1,-1.6) 5(-1.2,-1.6) 6(-2.3,-1.6) 7(-3.4,-1.6) 8(-4.5,-1.6)
  rect 1.8x2.2 smd: 9(-6.8,4.1) 10(-6.8,-4.1) 11(6.8,-4.1) 12(6.8,4.1)
  silkscreen extent -6.8,-6.65 6.8,7.75
TSOP-54_L22.2-W10.2-P0.80-LS11.8-BL [mm]
  oval 0.5x1.8 smd: 1(-10.4,-5.642) 2(-9.6,-5.642) 3(-8.8,-5.642) 4(-8,-5.642) 5(-7.2,-5.642) 6(-6.4,-5.642) 7(-5.6,-5.642) 8(-4.8,-5.642) 9(-4,-5.642) 10(-3.2,-5.642) 11(-2.4,-5.642) 12(-1.6,-5.642) 13(-0.8,-5.642) 14(0,-5.642) 15(0.8,-5.642) 16(1.6,-5.642) 17(2.4,-5.642) 18(3.2,-5.642) 19(4,-5.642) 20(4.8,-5.642) 21(5.6,-5.642) 22(6.4,-5.642) 23(7.2,-5.642) 24(8,-5.642) 25(8.8,-5.642) 26(9.6,-5.642) 27(10.4,-5.642) 28(10.4,5.642) 29(9.6,5.642) 30(8.8,5.642) 31(8,5.642) 32(7.2,5.642) 33(6.4,5.642) 34(5.6,5.642) 35(4.8,5.642) 36(4,5.642) 37(3.2,5.642) 38(2.4,5.642) 39(1.6,5.642) 40(0.8,5.642) 41(0,5.642) 42(-0.8,5.642) 43(-1.6,5.642) 44(-2.4,5.642) 45(-3.2,5.642) 46(-4,5.642) 47(-4.8,5.642) 48(-5.6,5.642) 49(-6.4,5.642) 50(-7.2,5.642) 51(-8,5.642) 52(-8.8,5.642) 53(-9.6,5.642) 54(-10.4,5.642)
  silkscreen extent -11.23,-5.79 11.19,4.65
USB-C-SMD_TYPE-C16PIN [mm]
  oval 1x2.1 hole 0.6 slot 1.7 at 90 deg: 1(-4.32,1.787) 2(4.32,1.787)
  oval 1x1.8 hole 0.6 slot 1.4 at 90 deg: 3(-4.32,-2.362) 4(4.32,-2.362)
  rect 0.6x1.15 smd: A1B12(-3.2,2.362) A4B9(-2.4,2.362) B1A12(3.2,2.362) B4A9(2.4,2.362)
  rect 0.3x1.15 smd: A5(-1.25,2.362) A6(-0.25,2.362) A7(0.25,2.362) A8(1.25,2.362) B5(1.75,2.362) B6(0.75,2.362) B7(-0.75,2.362) B8(-1.75,2.362)
  Board Outline Layer circle w0.005: c2.89,1.288 r0.325
  Board Outline Layer circle w0.005: c-2.89,1.288 r0.325
  Board Outline Layer region: 2.89,1.613 3.031,1.581 3.144,1.491 3.207,1.36 3.207,1.216 3.144,1.085 3.031,0.995 2.89,0.963 2.89,0.963 2.749,0.995 2.636,1.085 2.573,1.216 2.573,1.36 2.636,1.491 2.749,1.581 2.89,1.613
  Board Outline Layer region: -2.89,1.613 -2.749,1.581 -2.636,1.491 -2.573,1.36 -2.573,1.216 -2.636,1.085 -2.749,0.995 -2.89,0.963 -2.89,0.963 -3.031,0.995 -3.144,1.085 -3.207,1.216 -3.207,1.36 -3.144,1.491 -3.031,1.581 -2.89,1.613
  Multi-Layer board cut-out: 2.89,1.613 3.031,1.581 3.144,1.491 3.207,1.36 3.207,1.216 3.144,1.085 3.031,0.995 2.89,0.963 2.89,0.963 2.749,0.995 2.636,1.085 2.573,1.216 2.573,1.36 2.636,1.491 2.749,1.581 2.89,1.613
  Multi-Layer board cut-out: -2.89,1.613 -2.749,1.581 -2.636,1.491 -2.573,1.36 -2.573,1.216 -2.636,1.085 -2.749,0.995 -2.89,0.963 -2.89,0.963 -3.031,0.995 -3.144,1.085 -3.207,1.216 -3.207,1.36 -3.144,1.491 -3.031,1.581 -2.89,1.613
  silkscreen extent -4.45,-5 4.45,0.52
WIRELM-SMD_ESP32-S3-WROOM-1 [mm]
  rect 1.5x0.9 smd: 1(-8.75,8.895) 2(-8.75,7.625) 3(-8.75,6.355) 4(-8.75,5.085) 5(-8.75,3.815) 6(-8.75,2.545) 7(-8.75,1.275) 8(-8.75,0.005) 9(-8.75,-1.265) 10(-8.75,-2.535) 11(-8.75,-3.805) 12(-8.75,-5.075) 13(-8.75,-6.345) 14(-8.75,-7.615) 27(8.75,-7.615) 28(8.75,-6.345) 29(8.75,-5.075) 30(8.75,-3.805) 31(8.75,-2.535) 32(8.75,-1.265) 33(8.75,0.005) 34(8.75,1.275) 35(8.75,2.545) 36(8.75,3.815) 37(8.75,5.085) 38(8.75,6.355) 39(8.75,7.625) 40(8.75,8.895)
  rect 0.9x1.5 smd: 15(-6.985,-8.895) 16(-5.715,-8.895) 17(-4.445,-8.895) 18(-3.175,-8.895) 19(-1.905,-8.895) 20(-0.635,-8.895) 21(0.635,-8.895) 22(1.905,-8.895) 23(3.175,-8.895) 24(4.445,-8.895) 25(5.715,-8.895) 26(6.985,-8.865)
  rect 0.9x0.9 smd: 41(-2.9,-0.225) 41(-2.9,1.175) 41(-2.9,2.575) 41(-1.5,2.575) 41(-1.5,-0.225) 41(-1.5,1.175) 41(-0.1,2.575) 41(-0.1,1.175) 41(-0.1,-0.225)
  silkscreen extent -9,-9.14 9.02,16.39

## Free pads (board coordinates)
  round 1.524 hole 0.914: 1(96.571,93.904) 1(107.493,117.018) 1(112.065,98.73)
  round 0.08 smd: 55(90.131,120.193) 55(91.364,123.622) 55(91.618,86.792) 55(92.253,86.284) 55(92.375,116.832) 55(93.396,116.51) 55(94.254,146.63) 55(94.285,86.284) 55(94.285,116.129) 55(96.298,82.747) 55(96.317,81.839) 55(113.208,157.15) 55(120.444,166.728) 55(121.549,166.687) 55(121.965,93.234) 55(123.445,95.264) 55(126.796,166.776) 55(127.919,166.471) 55(130.607,166.548) 55(133.147,166.548) 55(140.681,91.433) 55(142.081,91.393)
  round 0.08 smd far side: 55(92.126,119.05) 55(92.294,119.92) 55(93.673,117.376) 55(99.749,121.074) 55(108.89,126.014) 55(110.033,126.035) 55(110.16,137.846) 55(110.865,126.981) 55(111.811,127.407) 55(112.827,149.784) 55(113.335,150.546) 55(113.716,149.784) 55(114.351,150.673) 55(115.113,150.546)

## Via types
v1: diameter 0.4, hole 0.3, Top Layer to Bottom Layer, 261 vias
v2: diameter 0.61, hole 0.305, Top Layer to Bottom Layer, 16 vias

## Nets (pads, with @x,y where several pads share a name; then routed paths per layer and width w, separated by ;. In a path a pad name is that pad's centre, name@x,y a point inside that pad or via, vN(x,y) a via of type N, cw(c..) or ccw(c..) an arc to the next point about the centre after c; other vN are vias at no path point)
$1N8318: C15.2 U5.43 | length 1.4
  Top Layer w0.254: C15.2@129.532,148.768 129.769,148.531 U5.43@129.769,147.425
$1N8986: C16.2 U5.49 | length 1.5
  Top Layer w0.254: C16.2@124.649,148.757 124.969,148.437 U5.49@124.969,147.425
$1N9039: C14.1 U5.27 | length 0.7
  Top Layer w0.254: U5.27@141.769,136.141 141.842,136.068 C14.1@142.477,136.068
$1N9091: C13.1 U5.14 | length 1.5
  Top Layer w0.254: C13.1@131.369,134.671 U5.14@131.369,136.141
$1N9142: C12.1 U5.9 | length 1.4
  Top Layer w0.254: 126.924,134.925 127.369,135.37 U5.9@127.369,136.141
$1N9192: C11.1 U5.3 | length 1.4
  Top Layer w0.254: C11.1@122.42,134.798 122.569,134.947 U5.3@122.569,136.141
$1N9241: C10.1 U5.1 | length 1.5
  Top Layer w0.254: C10.1@120.969,134.798 U5.1@120.969,136.268
$1N9341: C8.1 C10.2 C11.2 C12.2 C13.2 C14.2 C15.1 C16.1 R1.2 | length 67.2
  Top Layer w0.254: C10.2@121.404,134.798 121.717,134.485 v1(121.717,134.311) 122.03,134.624 C11.2@122.03,134.798 ; v1(123.906,149.56) 124.373,149.093 C16.1@124.373,149.033 ; v1(126.162,134.163) C12.2@126.532,134.533 ; v1(128.662,149.189) 128.721,149.189 C15.1@129.142,148.768 ; v1(130.734,132.639) 130.861,132.512 133.02,132.512 134.036,133.528 v1(134.163,133.528) ; v1(131.369,133.655) C13.2@131.369,134.222 ; v1(132.258,150.546) 133.707,150.546 R1.2@133.782,150.471 ; C14.2@142.867,136.068 v1(142.867,136.576) ; C8.1@143.815,142.656 144.561,141.91 v1(145.339,141.91)
  Bottom Layer w0.254: v1(121.717,134.311) 121.865,134.163 v1(126.162,134.163) 129.21,134.163 v1(130.734,132.639) 130.734,133.02 v1(131.369,133.655) ; v1(123.906,149.56) 128.291,149.56 v1(128.662,149.189) 130.901,149.189 v1(132.258,150.546) 142.867,139.937 v1(142.867,136.576) ; v1(134.163,133.528) 139.819,133.528 v1(142.867,136.576) ; v1(145.339,141.91) 145.974,141.275 145.974,138.989 143.561,136.576 v1(142.867,136.576)
$1N9437: R1.1 U5.37 | length 2.5
  Top Layer w0.254: R1.1@133.782,149.605 134.569,148.818 U5.37@134.569,147.425
$1N11348: R2.1 U5.38 | length 19.3
  Top Layer w0.1: R2.1@116.943,142.926 130.226,142.926 133.782,146.482 133.782,147.412 U5.38@133.769,147.425
$1N11975: R7.1 U2.3 | length 1.5
  Top Layer w0.254: U2.3@95.042,97.473 95.047,97.468 R7.1@95.047,95.988
$1N12553: R10.2 USB1.B5 | length 1.7
  Top Layer w0.254: USB1.B5@90.678,84.788 91.909,84.788 R10.2@92.262,85.141
$1N12557: R9.2 USB1.A5 | length 2
  Top Layer w0.254: USB1.A5@90.678,87.788 91.716,87.788 R9.2@92.38,88.452
$1N14416: C18.2 L1.1 U6.5 | length 7.6
  Top Layer w0.254: L1.1@96.238,86.538 96.238,88.697 95.809,89.126 95.809,91.778 96.091,92.061 96.311,92.061 C18.2@96.317,92.067 97.829,92.067 U6.5@97.888,92.126
$1N14459: C18.1 U6.6 | length 1.8
  Top Layer w0.254: C18.1@96.317,91.677 96.818,91.176 U6.6@97.888,91.176
$1N14567: C19.1 R11.1 R12.2 U6.1 | length 11.6
  Top Layer w0.254: U6.1@100.588,91.176 104.571,91.176 C19.1@105.715,90.032 108.71,90.032 R11.1@108.763,90.085 111.667,90.085 R12.2@111.684,90.103
$1N14571: C19.2 C22.2 C23.2 L1.2 R11.2 | length 16.2
  Top Layer w0.254: L1.2@102.238,86.538 103.621,86.538 C19.2@105.715,88.632 108.71,88.632 R11.2@108.763,88.579 108.816,88.632 C23.2@114.478,88.632 C22.2@117.526,88.632
$1N16832: C24.2 L2.1 U7.5 | length 5.3
  Top Layer w0.254: C24.2@130.099,93.328 129.278,92.507 U7.5@128.782,92.507 128.788,92.501 L2.1@132.417,92.501
$1N16833: C24.1 U7.6 | length 1.4
  Top Layer w0.254: U7.6@128.782,93.457 129.037,93.712 130.093,93.712 C24.1@130.099,93.718
$1N16834: C25.1 R14.2 R15.1 U7.1 | length 30.7
  Top Layer w0.254: U7.1@126.082,93.457 126.377,93.457 127.432,92.402 127.432,91.662 135.731,83.363 142.799,83.363 143.667,84.231 R14.2@143.667,87.983 142.651,87.983 R15.1@142.135,87.466 142.081,87.413 C25.1@142.081,84.799
$1N17349: C29.2 C30.2 C31.1 C32.1 | length 3.8
  Top Layer w0.254: C30.2@124.325,98.73 125.4,97.655 C32.1@125.4,96.354 124.489,96.354 C29.2@124.452,96.317
$1N24377: R23.2 U1.P10 | length 20.2
  Top Layer w0.1: R23.2@91.289,140.767 93.904,140.767 94.01,140.661 94.01,140.473 94.626,139.857 96.846,139.857 v1(97.206,139.497)
  Top Layer w0.254: U1.P10@109.328,138.526 109.652,138.85 v1@109.652,138.862
  Bottom Layer w0.254: v1(97.206,139.497) 97.339,139.364 100.968,139.364 101.045,139.441 101.045,139.568 101.326,139.849 107.619,139.849 108.485,138.983 109.192,138.983 109.292,138.883 v1(109.673,138.883)
$1N24422: R24.2 U1.N10 | length 23.9
  Top Layer w0.1: v1(94.92,139.455) 96.679,139.455 97.039,139.095 97.373,139.095 97.733,139.455 97.926,139.455 99.17,140.699 99.17,140.704 99.806,141.34 100.599,141.34 101.431,140.508 104.054,140.508 104.146,140.416 104.146,139.968 104.37,139.744 105.486,139.744 105.493,139.751 105.963,139.751 105.97,139.744 106.286,139.744 106.51,139.968 106.51,140.326 106.692,140.508 107.886,140.508 108.146,140.248 108.146,139.168 108.37,138.944 108.946,138.944 U1.N10@109.328,139.326
  Top Layer w0.254: R24.2@93.448,143.307 94.337,142.418 v1(95.174,142.418)
  Bottom Layer w0.1: v1(94.92,139.455) 94.666,139.709 94.666,140.334 95.374,141.042 95.374,141.466 95.301,141.539 95.301,141.783 95.174,141.91 v1(95.174,142.418)
$1N24492: R25.2 U1.R10 | length 17.1
  Top Layer w0.1: R25.2@100.254,130.405 100.254,137.338 101.016,138.1 101.962,138.1 101.97,138.108 102.286,138.108 102.51,137.884 102.51,137.395 102.567,137.338 102.667,137.338 102.673,137.344 108.686,137.344 109.068,137.726 U1.R10@109.328,137.726
$1N29790: R26.2 U2.5 | length 57.9
  Top Layer w0.1: v1(85.133,137.592) 85.395,137.854 R26.2@85.395,138.429 ; U2.5@97.582,97.473 97.587,97.468 v1(97.587,96.444)
  Bottom Layer w0.1: v1(85.133,137.592) 85.014,137.473 85.014,137.16 84.885,137.032 84.885,136.76 85.014,136.632 85.014,136.36 84.885,136.232 84.885,135.96 85.014,135.832 85.014,135.56 84.885,135.432 84.885,135.16 85.014,135.032 85.014,134.76 84.885,134.632 84.885,134.36 85.014,134.232 85.014,133.96 84.885,133.832 84.885,133.56 85.014,133.432 85.014,133.16 84.885,133.032 84.885,132.76 85.014,132.632 85.014,95.555 85.268,95.301 95.046,95.301 96.189,96.444 v1(97.587,96.444)
$1N29833: R27.2 U2.6 | length 59.2
  Top Layer w0.1: v1(85.812,137.556) 85.812,137.703 R27.2@86.538,138.429 ; v1(98.852,96.444) U2.6@98.852,97.473
  Bottom Layer w0.1: v1(85.812,137.556) 85.522,137.266 85.522,136.995 85.451,136.924 85.314,136.924 85.243,136.854 85.243,136.595 85.314,136.524 85.451,136.524 85.522,136.454 85.522,136.195 85.451,136.124 85.314,136.124 85.243,136.054 85.243,135.795 85.314,135.724 85.451,135.724 85.522,135.654 85.522,135.395 85.451,135.324 85.314,135.324 85.243,135.254 85.243,134.995 85.314,134.924 85.451,134.924 85.522,134.854 85.522,134.595 85.451,134.524 85.314,134.524 85.243,134.454 85.243,134.195 85.314,134.124 85.451,134.124 85.522,134.054 85.522,133.795 85.451,133.724 85.314,133.724 85.243,133.654 85.243,133.395 85.314,133.324 85.451,133.324 85.522,133.254 85.522,132.995 85.451,132.924 85.314,132.924 85.243,132.854 85.243,132.595 85.314,132.524 85.451,132.524 85.522,132.454 85.522,132.195 85.451,132.124 85.314,132.124 85.243,132.054 85.243,131.795 85.314,131.724 85.451,131.724 85.522,131.654 85.522,131.431 85.451,131.36 85.314,131.36 85.243,131.29 85.243,131.031 85.314,130.96 85.451,130.96 85.522,130.89 85.522,130.631 85.451,130.56 85.314,130.56 85.243,130.49 85.243,130.231 85.314,130.16 85.451,130.16 85.522,130.09 85.522,129.831 85.451,129.76 85.314,129.76 85.243,129.69 85.243,129.431 85.314,129.36 85.451,129.36 85.522,129.29 85.522,98.984 87.3,97.206 98.09,97.206 v1(98.852,96.444)
$1N29916: R29.2 U2.9 | length 59.1
  Top Layer w0.1: v1(87.123,137.388) 87.478,137.388 88.52,138.429 R29.2@88.824,138.429 ; v1(101.27,99.238) 102.662,97.846 U2.9@102.662,97.473
  Bottom Layer w0.1: v1(87.123,137.388) 86.921,137.186 86.865,137.186 86.592,136.913 86.592,136.616 86.663,136.546 86.848,136.546 86.919,136.475 86.919,136.216 86.848,136.146 86.663,136.146 86.592,136.075 86.592,135.816 86.663,135.746 86.848,135.746 86.919,135.675 86.919,135.416 86.848,135.346 86.663,135.346 86.592,135.275 86.592,135.016 86.663,134.946 86.848,134.946 86.919,134.875 86.919,134.616 86.848,134.546 86.663,134.546 86.592,134.475 86.592,134.216 86.663,134.146 86.848,134.146 86.919,134.075 86.919,133.816 86.848,133.746 86.663,133.746 86.592,133.675 86.592,133.416 86.663,133.346 86.848,133.346 86.919,133.275 86.919,133.016 86.848,132.946 86.663,132.946 86.592,132.875 86.592,132.661 86.663,132.591 86.848,132.591 86.919,132.52 86.919,132.261 86.848,132.191 86.663,132.191 86.592,132.12 86.592,131.861 86.663,131.791 86.848,131.791 86.919,131.72 86.919,131.461 86.848,131.391 86.663,131.391 86.592,131.32 86.592,102.486 89.84,99.238 v1(101.27,99.238)
$1N29959: R30.2 U2.12 | length 59.5
  Top Layer w0.1: v1(88.062,137.338) 88.876,137.338 R30.2@89.967,138.429 ; v1(98.603,100.762) 105.461,100.762 106.472,99.751 U2.12@106.472,97.473
  Bottom Layer w0.1: v1(88.062,137.338) 87.642,137.338 87.29,136.986 87.29,136.976 87.246,136.932 87.246,103.991 90.475,100.762 v1(98.603,100.762)
$1N30002: R31.2 U2.23 | length 58.9
  Top Layer w0.1: v1(88.443,110.414) 108.255,110.414 109.271,109.398 U2.23@110.165,109.398 ; v1@89.332,137.338 90.019,137.338 R31.2@91.11,138.429
  Bottom Layer w0.1: v1(88.443,110.414) 87.847,111.01 87.847,126.348 87.776,126.419 87.546,126.419 87.475,126.489 87.475,126.748 87.546,126.819 87.776,126.819 87.847,126.889 87.847,127.148 87.776,127.219 87.546,127.219 87.475,127.289 87.475,127.548 87.546,127.619 87.776,127.619 87.847,127.689 87.847,127.948 87.776,128.019 87.546,128.019 87.475,128.089 87.475,128.348 87.546,128.419 87.776,128.419 87.847,128.489 87.847,128.748 87.776,128.819 87.546,128.819 87.475,128.889 87.475,129.148 87.546,129.219 87.776,129.219 87.847,129.289 87.847,129.548 87.776,129.619 87.546,129.619 87.475,129.689 87.475,129.948 87.546,130.019 87.776,130.019 87.847,130.089 87.847,130.348 87.776,130.419 87.546,130.419 87.475,130.489 87.475,130.748 87.546,130.819 87.776,130.819 87.847,130.889 87.847,131.148 87.776,131.219 87.546,131.219 87.475,131.289 87.475,131.548 87.546,131.619 87.776,131.619 87.847,131.689 87.847,131.948 87.776,132.019 87.546,132.019 87.475,132.089 87.475,132.348 87.546,132.419 87.776,132.419 87.847,132.489 87.847,132.748 87.776,132.819 87.546,132.819 87.475,132.889 87.475,133.148 87.546,133.219 87.776,133.219 87.847,133.289 87.847,133.548 87.776,133.619 87.546,133.619 87.475,133.689 87.475,133.948 87.546,134.019 87.776,134.019 87.847,134.089 87.847,134.886 87.446,135.287 87.446,136.57 87.725,136.849 88.574,136.849 89.007,137.282 v1(89.388,137.282)
$1N30085: R34.2 U2.25 | length 59.4
  Top Layer w0.1: v1@91.491,137.084 92.178,137.084 93.396,138.302 R34.2@93.396,138.429 ; v1(91.999,112.065) 92.126,111.938 92.934,111.938 93.005,112.009 93.005,112.248 93.076,112.319 93.334,112.319 93.405,112.248 93.405,112.009 93.476,111.938 93.734,111.938 93.805,112.009 93.805,112.248 93.876,112.319 94.134,112.319 94.205,112.248 94.205,112.009 94.276,111.938 94.534,111.938 94.605,112.009 94.605,112.248 94.676,112.319 94.934,112.319 95.005,112.248 95.005,112.009 95.076,111.938 95.334,111.938 95.405,112.009 95.405,112.248 95.476,112.319 95.734,112.319 95.805,112.248 95.805,112.009 95.876,111.938 96.134,111.938 96.205,112.009 96.205,112.248 96.276,112.319 96.534,112.319 96.605,112.248 96.605,112.009 96.676,111.938 U2.25@110.165,111.938
  Bottom Layer w0.1: v1(91.484,137.091) 89.459,135.067 89.459,134.746 89.53,134.675 89.896,134.675 89.967,134.605 89.967,134.346 89.896,134.275 89.53,134.275 89.459,134.205 89.459,133.946 89.53,133.875 89.886,133.875 89.957,133.805 89.957,133.546 89.886,133.475 89.53,133.475 89.459,133.405 89.459,133.146 89.53,133.075 89.895,133.075 89.966,133.005 89.966,132.746 89.895,132.675 89.53,132.675 89.459,132.605 89.459,132.346 89.53,132.275 89.886,132.275 89.957,132.205 89.957,131.946 89.886,131.875 89.53,131.875 89.459,131.805 89.459,131.546 89.53,131.475 89.931,131.475 90.001,131.405 90.001,131.146 89.931,131.075 89.53,131.075 89.459,131.005 89.459,130.746 89.53,130.675 89.958,130.675 90.028,130.605 90.028,130.346 89.958,130.275 89.53,130.275 89.459,130.205 89.459,129.946 89.53,129.875 90.003,129.875 90.073,129.805 90.073,129.546 90.003,129.475 89.53,129.475 89.459,129.405 89.459,129.191 89.53,129.12 90.009,129.12 90.08,129.049 90.08,128.791 90.009,128.72 89.53,128.72 89.459,128.649 89.459,128.391 89.53,128.32 90.009,128.32 90.08,128.249 90.08,127.991 90.009,127.92 89.53,127.92 89.151,127.541 89.151,114.913 v1(91.999,112.065)
$1N30089: R32.2 U2.24 | length 59.6
  Top Layer w0.1: v1(90.475,137.211) 91.035,137.211 R32.2@92.253,138.429 ; v1(91.745,111.43) 108.128,111.43 108.89,110.668 U2.24@110.165,110.668
  Bottom Layer w0.1: v1(90.475,137.211) 89.913,136.649 88.912,136.649 88.316,136.053 88.316,134.321 88.387,134.251 88.88,134.251 88.951,134.18 88.951,133.921 88.88,133.851 88.387,133.851 88.316,133.78 88.316,133.521 88.387,133.451 88.88,133.451 88.951,133.38 88.951,133.121 88.88,133.051 88.387,133.051 88.316,132.98 88.316,132.721 88.387,132.651 88.88,132.651 88.951,132.58 88.951,132.321 88.88,132.251 88.387,132.251 88.316,132.18 88.316,131.921 88.387,131.851 88.88,131.851 88.951,131.78 88.951,131.521 88.88,131.451 88.387,131.451 88.316,131.38 88.316,131.121 88.387,131.051 88.88,131.051 88.951,130.98 88.951,130.721 88.88,130.651 88.387,130.651 88.316,130.58 88.316,130.321 88.387,130.251 88.88,130.251 88.951,130.18 88.951,129.921 88.88,129.851 88.387,129.851 88.316,129.78 88.316,129.521 88.387,129.451 88.88,129.451 88.951,129.38 88.951,129.121 88.88,129.051 88.387,129.051 88.316,128.98 88.316,128.721 88.387,128.651 88.88,128.651 88.951,128.58 88.951,128.321 88.88,128.251 88.387,128.251 88.316,128.18 88.316,127.921 88.387,127.851 88.88,127.851 88.951,127.78 88.951,127.521 88.88,127.451 88.387,127.451 88.316,127.38 88.316,114.859 v1(91.745,111.43)
$1N30093: R28.2 U2.7 | length 59.1
  Top Layer w0.1: v1(86.444,137.465) 86.505,137.465 87.47,138.429 R28.2@87.681,138.429 ; U2.7@100.122,97.473 v1(100.122,98.476)
  Bottom Layer w0.1: v1(86.444,137.465) 85.776,136.797 85.776,136.553 85.847,136.482 85.959,136.482 86.03,136.411 86.03,136.153 85.959,136.082 85.847,136.082 85.776,136.011 85.776,135.753 85.847,135.682 85.959,135.682 86.03,135.611 86.03,135.353 85.959,135.282 85.847,135.282 85.776,135.211 85.776,134.953 85.847,134.882 85.959,134.882 86.03,134.811 86.03,134.553 85.959,134.482 85.847,134.482 85.776,134.411 85.776,134.153 85.847,134.082 85.959,134.082 86.03,134.011 86.03,133.753 85.959,133.682 85.847,133.682 85.776,133.611 85.776,133.353 85.847,133.282 85.959,133.282 86.03,133.211 86.03,132.953 85.959,132.882 85.847,132.882 85.776,132.811 85.776,132.553 85.847,132.482 85.959,132.482 86.03,132.411 86.03,132.153 85.959,132.082 85.847,132.082 85.776,132.011 85.776,131.753 85.847,131.682 85.959,131.682 86.03,131.611 86.03,131.353 85.959,131.282 85.847,131.282 85.776,131.211 85.776,130.961 85.847,130.89 86.086,130.89 86.157,130.819 86.157,130.561 86.086,130.49 85.847,130.49 85.776,130.419 85.776,130.161 85.847,130.09 86.086,130.09 86.157,130.019 86.157,129.761 86.086,129.69 85.847,129.69 85.776,129.619 85.776,99.746 87.046,98.476 v1(100.122,98.476)
$1N33205: P1.8 R35.1 | length 5.1
  Top Layer w0.254: P1.8@90.08,125.695 90.101,125.673 91.689,125.673 91.786,125.576 R35.1@95.108,125.576
$1N36431: C37.2 U1.F6 | length 1.9
  Top Layer w0.1: v1(104.968,145.333) 104.994,145.308 105.486,145.308 105.868,144.926 U1.F6@106.128,144.926
  Bottom Layer w0.1: v1(104.968,145.333) 105.355,145.72 C37.2@105.393,145.72
$1N36495: C38.2 U1.F7 | length 1
  Top Layer w0.1: U1.F7@106.928,144.926 v1@107.309,145.307
  Bottom Layer w0.1: v1(107.334,145.307) 107.425,145.398 C38.2@107.425,145.72
$1N36552: C39.2 U1.F10 | length 1.7
  Top Layer w0.1: v1(108.928,146.079) 108.928,145.326 U1.F10@109.328,144.926
  Bottom Layer w0.1: v1(108.928,146.079) 108.949,146.099 C39.2@108.949,146.482
$1N36571: C40.2 U1.F11 | length 1
  Top Layer w0.1: v1(109.854,144.604) 110.128,144.878 U1.F11@110.128,144.926
  Bottom Layer w0.1: v1(109.854,144.604) 110.192,144.604 110.346,144.45
$1N36646: C41.2 U1.G6 | length 1.1
  Top Layer w0.1: U1.G6@106.128,144.126 106.528,144.526 v1(106.528,144.574)
  Bottom Layer w0.1: C41.2@106.35,144.137 106.528,144.315 v1(106.528,144.574)
$1N36690: C42.2 U1.G7 | length 1.6
  Top Layer w0.1: U1.G7@106.928,144.126 106.928,144.174 v1(107.328,144.574)
  Bottom Layer w0.1: v1(107.328,144.574) 107.555,144.574 107.678,144.451 107.678,144.391 107.914,144.155 107.974,144.155 C42.2@108.06,144.069
$1N36752: C43.2 U1.G9 | length 1.3
  Top Layer w0.1: U1.G9@108.528,144.126 108.852,144.45 v1(108.89,144.45)
  Bottom Layer w0.1: v1(108.89,144.45) 109.189,144.749 109.189,144.791 109.203,144.805 C43.2@109.203,145.085
$1N36807: C44.2 U1.G11 | length 0.9
  Top Layer w0.1: v1(109.767,143.813) 110.08,144.126 U1.G11@110.128,144.126
  Bottom Layer w0.1: v1(109.767,143.813) 110.217,143.813 C44.2@110.219,143.815
$1N36895: C45.2 U1.H6 | length 1
  Top Layer w0.1: U1.H6@106.128,143.326 106.477,142.977 v1@106.477,142.926
  Bottom Layer w0.1: v1(106.577,142.925) 106.577,142.958 C45.2@106.858,143.239
$1N36953: C46.2 U1.H7 | length 1.3
  Top Layer w0.1: U1.H7@106.928,143.326 107.314,142.94 v1(107.314,142.893)
  Bottom Layer w0.1: v1(107.314,142.893) 107.601,143.18 C46.2@107.933,143.18
$1N37097: C47.2 U1.H11 | length 1
  Top Layer w0.1: v1@109.779,142.926 109.779,142.977 U1.H11@110.128,143.326
  Bottom Layer w0.1: C47.2@109.339,142.926 v1@109.776,142.926
  other v1: 109.777,142.928
$1N37150: C48.1 U1.L11 | length 1.3
  Top Layer w0.1: v1(109.779,141.275) U1.L11@110.128,140.926
  Bottom Layer w0.1: C48.1@109.72,140.513 109.779,140.572 v1(109.779,141.275)
$1N37245: C50.1 U1.L7 | length 1.8
  Top Layer w0.1: v1(105.728,141.374) 105.794,141.308 106.286,141.308 106.668,140.926 U1.L7@106.928,140.926
  Bottom Layer w0.1: C50.1@105.681,141.021 105.728,141.067 v1(105.728,141.374)
$1N37295: C51.1 U1.L6 | length 2.7
  Top Layer w0.1: v1(104.88,141.326) 104.91,141.296 104.91,140.804 105.201,140.513 105.715,140.513 U1.L6@106.128,140.926
  Bottom Layer w0.1: C51.1@104.259,141.275 104.829,141.275 v1(104.88,141.326)
$1N37345: C52.1 U1.K11 | length 1.2
  Top Layer w0.1: v1@109.652,142.037 109.817,142.037 U1.K11@110.128,141.726
  Bottom Layer w0.1: v1(109.711,142.096) 110.278,142.096 C52.1@110.287,142.105
$1N37361: C49.1 U1.L10 | length 0.9
  Top Layer w0.1: v1(109.017,141.275) 109.328,140.964 U1.L10@109.328,140.926
  Bottom Layer w0.1: C49.1@108.958,141.656 108.958,141.334 v1(109.017,141.275)
$1N37409: C53.1 U1.L9 | length 1.2
  Top Layer w0.1: v1(108.211,141.229) 108.225,141.229 U1.L9@108.528,140.926
  Bottom Layer w0.1: v1(108.211,141.229) 108.353,141.229 108.704,140.878 C53.1@108.704,140.767
$1N37470: C54.1 U1.L8 | length 1
  Top Layer w0.1: v1(107.357,141.247) 107.407,141.247 U1.L8@107.728,140.926
  Bottom Layer w0.1: 106.926,141.402 107.202,141.402 v1(107.357,141.247)
$1N37518: C55.1 U1.J11 | length 1.1
  Top Layer w0.1: U1.J11@110.128,142.526 110.528,142.926 v1(110.541,142.926)
  Bottom Layer w0.1: v1(110.541,142.926) C55.1@111.108,142.926
$1N37600: C56.1 U1.J6 | length 1.8
  Top Layer w0.1: v1@104.953,142.164 105.15,142.164 105.17,142.144 105.746,142.144 U1.J6@106.128,142.526
  Bottom Layer w0.1: C56.1@104.513,142.164 104.937,142.164 v1(104.945,142.156)
$1N37637: C57.1 U1.J7 | length 1.1
  Top Layer w0.1: U1.J7@106.928,142.526 107.239,142.215 v1@107.239,142.164
  Bottom Layer w0.1: v1(107.239,142.205) 107.679,142.645 107.679,142.672
$1N41066: C48.2 C50.2 C51.2 C52.2 C55.2 C56.2 C57.2 C59.1 | length 14.8
  Bottom Layer w0.1: C51.2@103.869,141.275 103.869,141.91 C56.2@104.123,142.164 104.148,142.164 104.206,142.106 104.206,141.97 104.324,141.852 104.46,141.852 104.584,141.728 105.047,141.728 105.282,141.493 105.282,141.03 C50.2@105.291,141.021 105.291,141.613 105.461,141.783 105.76,141.783 106.26,142.283 106.593,142.283 107.072,141.803 107.494,141.803 108.069,142.452 C57.2@108.069,142.545 109.144,142.545 109.342,142.347 109.342,142.295 109.309,142.262 109.309,141.802 109.434,141.677 109.946,141.677 110.056,141.567 110.266,141.567 110.287,141.588 ; C48.2@110.101,140.513 110.287,140.699 110.287,141.588 ; C59.1@112.192,144.131 112.192,143.62 C55.2@111.498,142.926 111.415,142.843 111.415,142.732 110.481,141.798 110.37,141.798 C52.2@110.287,141.715 110.287,141.588
$1N47813: C41.1 C42.1 C43.1 C61.1 | length 5.6
  Bottom Layer w0.1: C61.1@105.653,143.688 106.345,143.688 106.487,143.83 ; C41.1@106.35,143.747 106.35,143.815 106.365,143.83 106.487,143.83 ; C43.1@109.593,145.085 109.593,144.912 109.389,144.708 109.389,144.381 109.113,144.105 109.113,143.996 108.45,143.996 108.45,143.857 108.35,143.757 107.871,143.757 107.715,143.913 107.715,144.071 107.615,144.172 106.885,144.172 106.544,143.83 106.487,143.83
+1V1: C25.2 C27.2 C28.2 C49.2 C53.2 C54.2 C61.2 L2.2 pad.55@111.811,127.407 pad.55@140.681,91.433 R15.2 | length 81.7
  Top Layer w0.1: C25.2@140.681,84.799 C28.2@140.681,90.133 pad.55@140.681,91.433 C27.2@140.681,92.546
  Top Layer w0.254: v1(111.894,126.924) 138.417,100.401 L2.2@138.417,92.501 138.462,92.546 C27.2@140.681,92.546
  Bottom Layer w0.1: C61.2@104.253,143.688 103.429,142.864 103.429,141.021 103.81,140.64 106.686,140.64 106.873,140.827 ; C54.2@106.409,141.402 106.492,141.319 106.492,141.208 106.873,140.827 ; C49.2@108.568,141.656 108.001,141.656 107.841,141.496 107.841,141.427 107.809,141.396 107.809,141.062 108.044,140.827 ; pad.55@111.811,127.407 111.811,134.544 111.176,135.179 111.176,138.481 109.271,140.386 108.695,140.386 108.626,140.455 108.515,140.455 108.397,140.573 108.397,140.684 C53.2@108.314,140.767 108.254,140.827 108.044,140.827 ; 106.873,140.827 108.044,140.827
  Bottom Layer w0.254: pad.55@111.811,127.407 111.811,127.007 v1(111.894,126.924)
+1V8: C29.1 C32.2 C36.1 P1.10 pad.55@92.294,119.92 pad.55@123.445,95.264 U8.2 | length 66
  Top Layer w0.254: P1.10@90.08,126.695 91.092,126.695 v1(91.111,126.713) 91.154,126.67 C36.1@91.677,126.67 ; v1(94.412,118.161) 105.08,118.161 108.255,121.336 112.065,121.336 119.05,114.351 119.05,99.261 U8.2@121.965,96.346 ; C29.1@124.062,96.317 121.994,96.317 123.047,95.264 pad.55@123.445,95.264 C32.2@125.4,95.264
  Bottom Layer w0.254: v1(91.111,126.713) 90.729,126.331 90.729,121.485 pad.55@92.294,119.92 94.053,118.161 v1(94.412,118.161)
+3V3: C8.2 C17.2 C34.1 C35.1 C37.1 C38.1 C39.1 C40.1 C44.1 C45.1 C46.1 C47.1 C58.1 C58.2 C59.2 CARD1.4 H1.5 P1.4 P1.11 pad.55@91.364,123.622 pad.55@94.254,146.63 pad.55@130.607,166.548 R3.1 R4.1 R5.2 R7.2 R16.2 R17.2 R18.2 R19.2 R20.2 R21.2 R22.2 R23.1 U2.2 U9.1 U9.4 | length 69.1
  Top Layer w0.1: v1(89.588,140.524) 89.831,140.767 R23.1@90.423,140.767 ; P1.11@90.08,127.194 92.043,127.194 92.576,126.662 92.576,126.549 92.694,126.431 92.805,126.431 C35.1@92.888,126.348 ; pad.55@94.254,146.63 v1(94.741,147.117) 95.433,147.117 95.435,147.119 ; v1(95.301,149.276) R18.2@96.326,149.276 ; v1(95.428,143.222) 95.513,143.307 R17.2@96.326,143.307 ; v1@96.326,150.546 R19.2@96.326,151.943
  Top Layer w0.254: P1.11@90.08,127.194 89.285,127.194 88.697,126.606 88.697,124.283 89.214,123.765 90.009,123.765 P1.4@90.08,123.695 91.356,123.695 v1(91.999,123.695) 92.072,123.622 C34.1@92.693,123.622 ; CARD1.4@93.423,161.011 93.423,149.131 95.435,147.119 R20.2@96.326,146.228 ; U2.2@93.772,97.473 93.65,97.351 v1(93.65,94.539) 94.464,94.539 R7.2@95.047,95.122 99.642,95.122 R5.2@100.456,95.936 ; R16.2@96.322,140.589 96.397,140.513 v1(96.952,140.513) ; R21.2@103.937,94.614 R22.2@105.207,94.614 104.572,93.979 v1(104.572,93.523) ; v1(108.763,160.071) 110.09,160.071 ; U9.1@110.965,159.196 110.09,160.071 ; U9.4@110.965,160.946 110.09,160.071 ; R3.1@112.752,108.128 112.827,108.203 v1(112.827,109.017) ; v1(112.827,99.873) R4.1@112.827,100.837 ; v1(143.815,139.116) C8.2@143.815,140.656
  Top Layer w1: pad.55@130.607,166.548 H1.5@130.607,168.58
  Bottom Layer w0.1: v1@105.715,146.228 105.783,146.16 C37.1@105.783,145.72 ; C45.1@106.858,143.629 107.193,143.629 v1(107.313,143.749) 107.57,143.492 108.122,143.492 108.24,143.374 108.24,143.263 C46.1@108.323,143.18 108.695,143.18 C47.1@108.949,142.926 ; C38.1@107.815,145.72 108.718,145.72 108.761,145.677 109.094,145.677 109.33,145.912 109.33,146.473 C39.1@109.339,146.482 109.42,146.482 v1(109.76,146.141) 110.857,147.238 C58.2@110.857,147.244 C58.1@112.257,147.244 112.257,145.596 C59.2@112.192,145.531 111.944,145.531 C40.1@110.863,144.45 110.863,144.069 C44.1@110.609,143.815
  other v1: 95.174,140.273 105.715,146.161 112.134,146.169 96.292,150.513
+5V: C20.2 C26.2 C30.1 C31.2 C33.2 pad.55@96.298,82.747 U6.2 U6.3 U7.2 U7.3 U8.3 USB1.A4B9 USB1.B4A9 | length 71.9
  Top Layer w0.254: USB1.A4B9@90.678,88.938 90.081,88.938 88.443,87.3 88.443,85.904 89.988,84.359 90.457,84.359 USB1.B4A9@90.678,84.138 92.008,84.138 ; C33.2@92.396,82.22 92.396,83.75 92.008,84.138 ; 95.047,83.998 pad.55@96.298,82.747 96.952,82.093 C20.2@97.522,82.093 ; U6.3@100.588,93.076 U6.2@100.588,92.126 ; U8.3@121.965,98.646 122.268,98.646 U8.3@122.352,98.73 ; C30.1@123.935,98.73 U8.3@122.352,98.73 ; U7.2@126.082,92.507 U7.3@126.082,91.557 125.956,91.683 C26.2@123.876,91.683 ; 92.008,84.138 97.219,84.138 98.984,85.903 98.984,90.856 100.254,92.126 U6.2@100.588,92.126 ; U6.2@100.588,92.126 100.754,92.292 123.267,92.292 C26.2@123.876,91.683 ; U8.3@122.352,98.73 123.749,100.127 125.019,100.127 126.453,98.693 C31.2@126.453,97.714 126.453,95.073 123.876,92.496 C26.2@123.876,91.683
